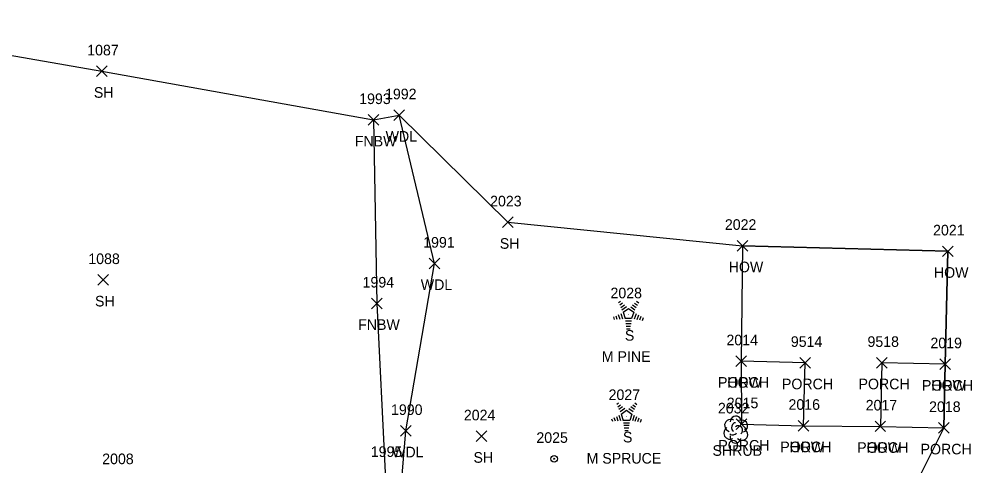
# Model space of a CAD drawing. Extents: x 1482574 to 1485769, y 580696 to 595649.
# Drawn here: x 1485377.8 to 1485557.8, y 582815.5 to 582899.9 of the extents above; entities that cross this region are included whole.
import ezdxf

# ---------------------------------------------------------------- set-up
doc = ezdxf.new("R2010")
doc.units = 0
for name, color, linetype in [('L_A', 7, 'Continuous'), ('L_C', 7, 'Continuous'), ('L_I', 7, 'Continuous'), ('L_TIC', 7, 'Continuous'), ('LANT', 7, 'Continuous'), ('LAWA', 7, 'Continuous'), ('LBC', 7, 'Continuous'), ('LBF', 7, 'Continuous'), ('LFNC', 7, 'Continuous'), ('LSH', 7, 'Continuous'), ('LSOGP', 7, 'Continuous'), ('LTC', 7, 'Continuous')]:
    doc.layers.add(name, color=color, linetype=linetype)

msp = doc.modelspace()

# ---------------------------------------------------------------- linework, layer by layer
at = {"layer": 'L_TIC'}
for points in [[(1485392.45, 582889.05), (1485394.45, 582891.05)], [(1485394.45, 582889.05), (1485392.45, 582891.05)], [(1485448.63, 582880.76), (1485450.63, 582882.76)], [(1485450.63, 582880.76), (1485448.63, 582882.76)], [(1485443.76, 582879.87), (1485445.75, 582881.86)], [(1485445.75, 582879.87), (1485443.76, 582881.86)], [(1485469.13, 582860.54), (1485471.13, 582862.54)], [(1485471.13, 582860.54), (1485469.13, 582862.54)], [(1485513.48, 582856.11), (1485515.48, 582858.11)], [(1485515.48, 582856.11), (1485513.48, 582858.11)], [(1485552.25, 582855.06), (1485554.25, 582857.06)], [(1485554.25, 582855.06), (1485552.25, 582857.06)], [(1485455.27, 582852.75), (1485457.27, 582854.75)], [(1485457.27, 582852.75), (1485455.27, 582854.75)], [(1485392.67, 582849.65), (1485394.67, 582851.65)], [(1485394.67, 582849.65), (1485392.67, 582851.65)], [(1485444.39, 582845.22), (1485446.39, 582847.22)], [(1485446.39, 582845.22), (1485444.39, 582847.22)], [(1485513.21, 582834.31), (1485515.21, 582836.31)], [(1485515.21, 582834.31), (1485513.21, 582836.31)], [(1485513.21, 582834.31), (1485515.21, 582836.31)], [(1485515.21, 582834.31), (1485513.21, 582836.31)], [(1485525.29, 582834.01), (1485527.29, 582836.01)], [(1485527.29, 582834.01), (1485525.29, 582836.01)], [(1485539.77, 582834.01), (1485541.77, 582836.01)], [(1485541.77, 582834.01), (1485539.77, 582836.01)], [(1485551.75, 582833.75), (1485553.75, 582835.75)], [(1485553.75, 582833.75), (1485551.75, 582835.75)], [(1485551.75, 582833.75), (1485553.75, 582835.75)], [(1485553.75, 582833.75), (1485551.75, 582835.75)], [(1485449.85, 582821.16), (1485451.85, 582823.16)], [(1485451.85, 582821.16), (1485449.85, 582823.16)], [(1485513.28, 582822.43), (1485515.28, 582824.43)], [(1485515.28, 582822.43), (1485513.28, 582824.43)], [(1485524.99, 582822.13), (1485526.99, 582824.13)], [(1485526.99, 582822.13), (1485524.99, 582824.13)], [(1485524.99, 582822.13), (1485526.99, 582824.13)], [(1485526.99, 582822.13), (1485524.99, 582824.13)], [(1485539.51, 582822.01), (1485541.51, 582824.01)], [(1485541.51, 582822.01), (1485539.51, 582824.01)], [(1485539.51, 582822.01), (1485541.51, 582824.01)], [(1485541.51, 582822.01), (1485539.51, 582824.01)], [(1485551.49, 582821.72), (1485553.49, 582823.72)], [(1485553.49, 582821.72), (1485551.49, 582823.72)], [(1485464.17, 582820.14), (1485466.17, 582822.14)], [(1485466.17, 582820.14), (1485464.17, 582822.14)]]:
    msp.add_lwpolyline(points, dxfattribs=at)
at = {"layer": 'LANT'}
for radius in [0.625, 0.0833]:
    msp.add_circle((1485478.87, 582816.89), radius, dxfattribs=at)
at = {"layer": 'LAWA'}
msp.add_lwpolyline([(1485354.62, 582801.86), (1485388.81, 582799.44), (1485419.98, 582794.35), (1485448.39, 582792.59), (1485450.85, 582822.16), (1485456.27, 582853.75), (1485449.63, 582881.76)], dxfattribs=at)
at = {"layer": 'LBC'}
for points in [[(1485514.48, 582857.11), (1485514.21, 582835.31)], [(1485552.75, 582834.75), (1485553.25, 582856.06), (1485514.48, 582857.11)], [(1485525.99, 582823.13), (1485540.51, 582823.01)]]:
    msp.add_lwpolyline(points, dxfattribs=at)
at = {"layer": 'LBF'}
for points in [[(1485514.21, 582835.31), (1485514.28, 582823.43), (1485525.99, 582823.13), (1485526.29, 582835.01)], [(1485526.29, 582835.01), (1485514.21, 582835.31)], [(1485540.51, 582823.01), (1485552.49, 582822.72), (1485552.75, 582834.75), (1485540.77, 582835.01)], [(1485540.77, 582835.01), (1485540.51, 582823.01)]]:
    msp.add_lwpolyline(points, dxfattribs=at)
at = {"layer": 'LFNC'}
msp.add_lwpolyline([(1485444.75, 582880.86), (1485445.39, 582846.22), (1485446.94, 582814.23), (1485447.63, 582798.73), (1485410.11, 582801.55), (1485371.33, 582804.04), (1485332.31, 582804.55), (1485297.48, 582804.12), (1485260.22, 582807.56), (1485224.34, 582807.64), (1485190.99, 582809.68), (1485155.77, 582811.06), (1485118.32, 582812.79), (1485079.67, 582814.76)], dxfattribs=at)
at = {"layer": 'LSH'}
msp.add_line((1485513.17, 582822.45), (1485513.17, 582822.45), dxfattribs=at)
msp.add_line((1485513.17, 582822.45), (1485513.17, 582822.45), dxfattribs=at)
msp.add_arc((1485513.22, 582823.88), 1.05, 335.5272, 180.9563, dxfattribs=at)
for centre, major_axis, ratio, start_param, end_param in [((1485512.38, 582823.12), (1.21, -0.51), 0.895232, 1.570796, 4.712389), ((1485512.96, 582822.91), (-0.208, -0.792), 0.645439, 3.141593, 6.283185), ((1485513.67, 582822.28), (-0.5, 0.667), 0.989748, 3.141593, 6.283185), ((1485514.21, 582823.03), (-1.14, -0.48), 0.949671, 1.570796, 4.712389), ((1485512.09, 582821.74), (0.58, -1.04), 0.959034, 3.141593, 6.283185), ((1485512.71, 582821.7), (-0.625, -0.083), 0.423636, 0, 3.141593), ((1485514.17, 582821.62), (-1.09, 0.79), 0.841452, 1.570796, 4.712389), ((1485513.17, 582820.95), (0.26, 1.06), 0.942809, 1.570796, 4.712389)]:
    msp.add_ellipse(centre, major_axis=major_axis, ratio=ratio, start_param=start_param, end_param=end_param, dxfattribs=at)
at = {"layer": 'LSOGP'}
msp.add_lwpolyline([(1485337.05, 582899.91), (1485393.45, 582890.05), (1485444.75, 582880.86), (1485449.63, 582881.76), (1485470.13, 582861.54), (1485514.48, 582857.11), (1485553.25, 582856.06), (1485552.75, 582834.75), (1485552.49, 582822.72), (1485545.76, 582809.25), (1485537.72, 582796.14), (1485531.28, 582787.96), (1485530.49, 582779.29), (1485529.76, 582768.73), (1485533.57, 582741.86), (1485488.82, 582735.36), (1485465.08, 582736.44), (1485434.74, 582726.33), (1485372.1, 582730.48)], dxfattribs=at)
at = {"layer": 'LTC'}
for p, q in [((1485491.06, 582846.4), (1485491.42, 582846.65)), ((1485494.46, 582846.64), (1485494.88, 582846.33)), ((1485491.27, 582845.93), (1485491.8, 582846.32)), ((1485491.48, 582845.47), (1485492.19, 582845.98)), ((1485491.69, 582845), (1485492.57, 582845.64)), ((1485491.92, 582844.55), (1485492.93, 582845.28)), ((1485492.93, 582845.28), (1485493.93, 582844.55)), ((1485493.35, 582845.59), (1485494.16, 582845)), ((1485493.72, 582845.94), (1485494.4, 582845.45)), ((1485494.09, 582846.29), (1485494.64, 582845.89)), ((1485490.1, 582843.68), (1485490.25, 582843.21)), ((1485490.55, 582843.89), (1485490.76, 582843.24)), ((1485491.01, 582844.11), (1485491.28, 582843.27)), ((1485491.46, 582844.33), (1485491.79, 582843.31)), ((1485491.92, 582844.55), (1485492.3, 582843.35)), ((1485493.53, 582843.35), (1485492.3, 582843.35)), ((1485493.93, 582844.55), (1485493.53, 582843.35)), ((1485494.36, 582844.28), (1485494.03, 582843.24)), ((1485494.81, 582844.03), (1485494.52, 582843.15)), ((1485495.25, 582843.78), (1485495.02, 582843.05)), ((1485495.7, 582843.53), (1485495.51, 582842.96)), ((1485493.5, 582842.85), (1485492.35, 582842.85)), ((1485493.41, 582842.35), (1485492.42, 582842.35)), ((1485493.33, 582841.85), (1485492.5, 582841.85)), ((1485493.25, 582841.35), (1485492.57, 582841.35)), ((1485490.7, 582827.18), (1485491.05, 582827.44)), ((1485490.91, 582826.72), (1485491.44, 582827.1)), ((1485491.12, 582826.25), (1485491.82, 582826.76)), ((1485493.36, 582826.73), (1485494.04, 582826.23)), ((1485493.73, 582827.08), (1485494.28, 582826.68)), ((1485494.1, 582827.42), (1485494.52, 582827.12)), ((1485490.64, 582824.9), (1485490.91, 582824.06)), ((1485491.1, 582825.11), (1485491.43, 582824.09)), ((1485491.33, 582825.79), (1485492.21, 582826.42)), ((1485491.55, 582825.33), (1485492.57, 582826.07)), ((1485491.55, 582825.33), (1485491.94, 582824.14)), ((1485492.57, 582826.07), (1485493.56, 582825.34)), ((1485492.99, 582826.38), (1485493.79, 582825.79)), ((1485493.56, 582825.34), (1485493.17, 582824.14)), ((1485494, 582825.07), (1485493.66, 582824.03)), ((1485489.73, 582824.46), (1485489.88, 582824)), ((1485490.19, 582824.68), (1485490.4, 582824.03)), ((1485493.17, 582824.14), (1485491.94, 582824.14)), ((1485493.13, 582823.64), (1485491.99, 582823.64)), ((1485493.05, 582823.14), (1485492.06, 582823.14)), ((1485494.44, 582824.82), (1485494.16, 582823.94)), ((1485494.89, 582824.57), (1485494.65, 582823.84)), ((1485495.33, 582824.32), (1485495.15, 582823.75)), ((1485492.97, 582822.64), (1485492.13, 582822.64)), ((1485492.88, 582822.14), (1485492.21, 582822.14))]:
    msp.add_line(p, q, dxfattribs=at)

# ---------------------------------------------------------------- texts
at = {"layer": 'L_A'}
for s, p in [('SH', (1485391.94, 582885.05)), ('FNBW', (1485441.23, 582875.86)), ('WDL', (1485447.05, 582876.76)), ('SH', (1485468.62, 582856.54)), ('HOW', (1485511.86, 582852.11)), ('HOW', (1485550.63, 582851.06)), ('WDL', (1485453.69, 582848.75)), ('SH', (1485392.15, 582845.65)), ('FNBW', (1485441.86, 582841.22)), ('S', (1485492.25, 582839.19)), ('PORCH', (1485509.84, 582830.31)), ('HOW', (1485511.6, 582830.31)), ('PORCH', (1485521.92, 582830.01)), ('PORCH', (1485536.39, 582830.01)), ('PORCH', (1485548.37, 582829.75)), ('HOW', (1485550.14, 582829.75)), ('S', (1485491.89, 582819.98)), ('SHRUB', (1485508.8, 582817.45)), ('PORCH', (1485509.9, 582818.43)), ('PORCH', (1485521.61, 582818.13)), ('HOW', (1485523.37, 582818.13)), ('PORCH', (1485536.14, 582818.01)), ('HOW', (1485537.9, 582818.01)), ('PORCH', (1485548.11, 582817.72)), ('WDL', (1485448.27, 582817.16)), ('SH', (1485463.65, 582816.14))]:
    msp.add_text(s, height=2, dxfattribs=at).set_placement(p)
at = {"layer": 'L_C'}
for s, p in [('M PINE', (1485487.89, 582835.19)), ('M SPRUCE', (1485485.01, 582815.98))]:
    msp.add_text(s, height=2, dxfattribs=at).set_placement(p)
at = {"layer": 'L_I'}
for s, p in [('1087', (1485390.68, 582893.05)), ('1992', (1485446.94, 582884.76)), ('1993', (1485442.06, 582883.86)), ('2023', (1485466.79, 582864.54)), ('2022', (1485511.14, 582860.11)), ('2021', (1485550.47, 582859.06)), ('1991', (1485454.15, 582856.75)), ('1088', (1485390.89, 582853.65)), ('1994', (1485442.7, 582849.22)), ('2028', (1485489.53, 582847.19)), ('2014', (1485511.44, 582838.31)), ('2014', (1485511.44, 582838.31)), ('9514', (1485523.6, 582838.01)), ('9518', (1485538.08, 582838.01)), ('2019', (1485549.97, 582837.75)), ('2019', (1485549.97, 582837.75)), ('2027', (1485489.17, 582827.98)), ('1990', (1485448.07, 582825.16)), ('2032', (1485509.83, 582825.45)), ('2015', (1485511.51, 582826.43)), ('2016', (1485523.16, 582826.13)), ('2016', (1485523.16, 582826.13)), ('2017', (1485537.74, 582826.01)), ('2017', (1485537.74, 582826.01)), ('2018', (1485549.72, 582825.72)), ('2024', (1485461.83, 582824.14)), ('2025', (1485475.53, 582819.89)), ('2008', (1485393.51, 582815.87)), ('1995', (1485444.25, 582817.23))]:
    msp.add_text(s, height=2, dxfattribs=at).set_placement(p)
at = {"layer": 'LTC'}
for p in [(1485492.81, 582844.29), (1485492.45, 582825.08)]:
    msp.add_text('.', height=1.04, rotation=270, dxfattribs=at).set_placement(p)

doc.saveas('drawing.dxf')
